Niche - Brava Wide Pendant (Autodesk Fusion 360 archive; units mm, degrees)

design "Brava Wide" references "PCB Single Pendant Canopy"
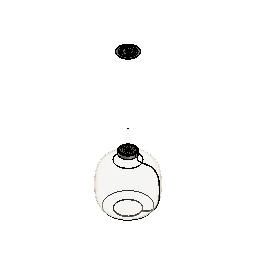
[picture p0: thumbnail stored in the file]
base_feature "Base Feature" bodies "Glass-Brava Wide"
external_derived "ExternalDerived1" bodies "Set Screw", "Strain Relief", "Lead-1", "Lead-2", "Lead-2.1", "Lead-1.1", "Coax", "Stem"
move "Move1"
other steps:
derived_base_feature "Derived Base Feature" bodies "Set Screw", "Strain Relief", "Lead-1", "Lead-2", "Lead-2.1", "Lead-1.1", "Coax", "Stem"
create_component "CreateComponent1"
named bodies: "Glass-Brava Wide", "Set Screw", "Strain Relief", "Lead-1", "Lead-2", "Lead-2.1", "Lead-1.1", "Coax", "Stem", "Strain Relief Cap", "Nylon Gripper (2)", "Cap", "Thumbscrew (1)", "Thumbscrew (2)", "Thumbscrew (3)", "Niche-PCB", "FJ-Plug Cover", "FJ-Plug", "FJ-Plug1.1", "FJ-Plug1.2", "FJ-Plug1.3", "Fj-Plug1.4", "Canopy", "FJ-Port", "FJ-Port1.1", "Spacer", "Universal Mount", "FJ-Port Cover", "Diffuser"

design "FJ Plug - PCB-Hardware"
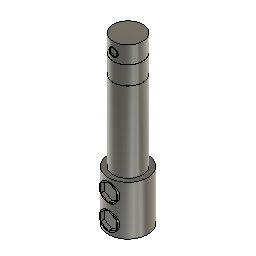
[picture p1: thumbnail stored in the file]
sketch "Sketch1" plane through (0, 0, 0) normal (0, 0, 1) x axis (1, 0, 0)
  circle C1 centre (0, 0) radius 3.048
  point P1 (0, 0)
  point P2 (0, 0)
  coincident P1 P2
  dimension "d1" diameter C1 = 6.096
extrude "Extrude1" new body sketch "Sketch1" along normal blind 34.036
sketch "Sketch2" plane through (0, 0, 0) normal (0, 0, 1) x axis (1, 0, 0)
  circle C1 centre (0, 0) radius 4.064
  point P1 (0, 0)
  point P2 (0, 0)
  coincident P1 P2
  dimension "d4" diameter C1 = 8.128
extrude "Extrude2" add sketch "Sketch2" along normal blind 10.16
sketch "Sketch3" plane through (0, 0, 0) normal (0, 1, 0) x axis (1, 0, 0)
  line L1 (6.35, 0) -> (-6.35, 0)
  line L2 (6.35, -30.48) -> (-6.35, -30.48)
  line L3 (2.54, -30.48) -> (6.35, -30.48)
  line L4 (2.54, -26.67) -> (2.54, -30.48)
  line L5 (6.35, -26.67) -> (2.54, -26.67)
  line L6 (6.35, -30.48) -> (6.35, -26.67)
  horizontal L1
  horizontal L3
  vertical L4
  horizontal L5
  vertical L6
  dimension "d7" = 30.48
revolve "Revolve1" sketch "Sketch3" AlongAngle 360
sketch "Sketch4" plane through (0, 0, 0) normal (0, 1, 0) x axis (1, 0, 0)
  line L1 (2.54, -30.48) -> (3.048, -30.48)
  line L2 (2.54, -26.67) -> (2.54, -30.48)
  line L3 (3.048, -26.67) -> (2.54, -26.67)
  line L4 (3.048, -30.48) -> (3.048, -26.67)
  horizontal L1
  vertical L2
  horizontal L3
  vertical L4
revolve "Revolve2" sketch "Sketch4" AlongAngle 360
chamfer "Chamfer1" distance 0.0254
chamfer "Chamfer2" distance 0.0254
hole "Hole1" HoleDepth 33.401 HoleDiameter 4.826 TipAngle 180
hole "Hole2" HoleDepth 3.81 HoleDiameter 1.778 TipAngle 180
hole "Hole3" HoleDepth 3.81 HoleDiameter 3.81 TipAngle 180
hole "Hole4" HoleDepth 3.81 HoleDiameter 3.81 TipAngle 180
sketch "Sketch5" plane through (0, 0, 0) normal (0, 1, 0) x axis (1, 0, 0)
  circle C1 centre (0, -32.0802) radius 0.889
  dimension "d24" diameter C1 = 1.778
extrude "Extrude3" new body sketch "Sketch5" along normal blind 1.778
move "Move1"
sketch "Sketch6" plane through (0, -3.048, 0) normal (0, -1, 0) x axis (1, 0, 0)
  line L1 (0.7259, 31.6611) -> (0, 31.242)
  line L2 (0.7259, 32.4993) -> (0.7259, 31.6611)
  line L3 (0, 32.9184) -> (0.7259, 32.4993)
  line L4 (-0.7259, 32.4993) -> (0, 32.9184)
  line L5 (-0.7259, 31.6611) -> (-0.7259, 32.4993)
  line L6 (0, 31.242) -> (-0.7259, 31.6611)
  circle C1 centre (0, 32.0802) radius 0.889
  point P2 (0, 32.0802)
  point P9 (0, 32.0802)
  coincident P2 P9
extrude "Extrude4" cut sketch "Sketch6" profile of L1 L2 L3 L4 L5 L6 against normal blind 0.254
sketch "Sketch7" plane through (0, 0, 0) normal (0, 1, 0) x axis (1, 0, 0)
  circle C1 centre (0, -2.4384) radius 1.905
  circle C2 centre (0, -7.5565) radius 1.905
  dimension "d29" diameter C1 = 3.81
  dimension "d30" diameter C2 = 3.81
extrude "Extrude5" new body sketch "Sketch7" profile of C2 along normal blind 3.81
move "Move2"
sketch "Sketch8" plane through (0, -4.064, 0) normal (0, -1, 0) x axis (1, 0, 0)
  line L1 (1.5948, 6.6357) -> (0, 5.715)
  line L2 (1.5948, 8.4772) -> (1.5948, 6.6357)
  line L3 (0, 9.398) -> (1.5948, 8.4772)
  line L4 (-1.5948, 8.4772) -> (0, 9.398)
  line L5 (-1.5948, 6.6357) -> (-1.5948, 8.4772)
  line L6 (0, 5.715) -> (-1.5948, 6.6357)
  circle C1 centre (0, 7.5565) radius 1.905
  point P2 (0, 7.5565)
  point P9 (0, 7.5565)
  coincident P2 P9
extrude "Extrude6" cut sketch "Sketch8" profile of L1 L2 L3 L4 L5 L6 against normal blind 0.762
copy_paste_bodies "CopyPasteBodies2"
move "Move4"
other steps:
base_feature "Base Feature"

design "Flask Petite"
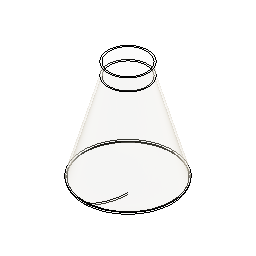
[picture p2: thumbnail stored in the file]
sketch "Sketch1" plane through (0, 0, 0) normal (1, 0, 0) x axis (0, 1, 0)
canvas "Canvas1"
sketch "Sketch2" plane through (0, 0, 0) normal (1, 0, 0) x axis (0, 1, 0)
  line L1 (-5.314, 187.093) -> (-57.384, 187.093)
  line L2 (-57.384, 155.343) -> (-57.384, 187.093)
  line L3 (-121.92, -71.12) -> (-57.384, 155.343)
  line L4 (-5.314, -112.5919) -> (-5.314, 187.093)
  curve K1 (-5.314, -112.5919) -> (-121.92, -74.8854)
  arc A1 centre (-115.3135, -73.0027) radius 6.8695 clockwise from (-121.92, -74.8854) to (-121.92, -71.12)
  point P2 (-57.384, 187.093)
  point P3 (-5.314, 187.093)
  point P4 (-57.384, 155.343)
  horizontal L1
  perpendicular L1 L2
  tangent L3 A1
  perpendicular L1 L4
  dimension "d1" distance P2 P3 = 52.07
  dimension "d2" distance P2 P4 = 31.75
revolve "Revolve1" sketch "Sketch2" AlongAngle 360
fillet "Fillet1" radius 5.08
shell "Shell1" innerThickness 4

design "PCB Single Pendant Canopy" references "Diffuser", "FJ Plug - PCB-Hardware", "FJ Cover - PCB-Hardware", "PCB Cap", "Flask Petite", "PCB Canopy"
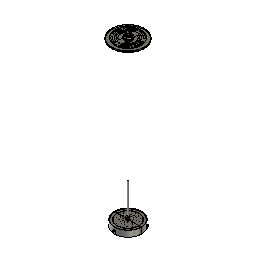
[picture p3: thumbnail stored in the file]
external_derived "ExternalDerived1" bodies "Nylon Gripper", "Set Screw", "Strain Relief", "Lead-1", "Lead-2", "Lead-2.1", "Lead-1.1", "Coax"
external_derived "ExternalDerived2" bodies "FJ-Plug Cover"
move "Move1"
move "Move2" TranslateX 3.175 TranslateY 0.254 TranslateZ 0
move "Move3" TranslateX 0 TranslateY 0 TranslateZ 1092.2
external_derived "ExternalDerived3" bodies "FJ-Plug", "FJ-Plug1.2", "FJ-Plug1.1", "FJ-Plug1.3", "Fj-Plug1.4"
move "Move4" TranslateX 0 TranslateY 0 TranslateZ 1117.6
external_derived "ExternalDerived4" bodies "Nylon Gripper", "Spacer", "Canopy", "FJ-Port", "FJ-Port1.1", "Universal Mount", "FJ-Port Cover", "Lead-1.1"
move "Move5"
move "Move6"
external_derived "ExternalDerived5" bodies "Diffuser"
move "Move7"
external_derived "ExternalDerived6" bodies "Thumbscrew (1)"
align "Align1"
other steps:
derived_base_feature "Derived Base Feature1"
derived_base_feature "Derived Base Feature2" bodies "FJ-Plug Cover"
derived_base_feature "Derived Base Feature3" bodies "FJ-Plug", "FJ-Plug1.1", "FJ-Plug1.2"
derived_base_feature "Derived Base Feature4" bodies "Body1 (1)", "Body1 (1) (1)", "Body2 (1)", "Body1 (2)", "Body1 (3)", "Body1 (4)", "Canopy", "FJ-Port"
derived_base_feature "Derived Base Feature5" bodies "Diffuser"
derived_base_feature "Derived Base Feature6" bodies "Body1", "Thumbscrew (1)"
named bodies: "Nylon Gripper", "Set Screw", "Strain Relief", "Lead-1", "Lead-2", "Lead-2.1", "Lead-1.1", "Coax", "Stem", "stem (2)", "Strain Relief Cap", "Nylon Gripper (2)", "Cap", "Thumbscrew (1)", "Thumbscrew (2)", "Thumbscrew (3)", "Niche-PCB", "FJ-Plug Cover", "FJ-Plug", "FJ-Plug1.1", "FJ-Plug1.2", "FJ-Plug1.3", "Fj-Plug1.4", "Body1 (1)", "Body1 (1) (1)", "Body2 (1)", "Body1 (2)", "Body1 (3)", "Body1 (4)", "Canopy", "FJ-Port", "FJ-Port1.1", "Spacer", "Universal Mount", "FJ-Port Cover", "Diffuser", "Body1"

design "FJ Female"
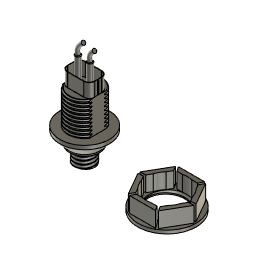
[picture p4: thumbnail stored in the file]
sketch "Sketch1" plane through (0, 0, 0) normal (0, 0, 1) x axis (1, 0, 0)
  circle C1 centre (0, 0) radius 4.445
  point P1 (0, 0)
  point P2 (0, 0)
  coincident P1 P2
  dimension "d1" diameter C1 = 8.89
extrude "Extrude1" new body sketch "Sketch1" along normal blind 6.858
sketch "Sketch2" plane through (0, 0, 6.858) normal (0, 0, 1) x axis (-1, 0, 0)
  circle C1 centre (0, 0) radius 4.445
  circle C2 centre (0, 0) radius 6.985
  point P1 (0, 0)
  point P3 (0, 0)
  coincident P1 P3
  dimension "d4" diameter C2 = 13.97
extrude "Extrude2" add sketch "Sketch2" along normal blind 1.27
work_plane "WorkPlane1" AlongDistance 5.08
sketch "Sketch3" plane through (0, 0, 13.208) normal (0, 0, 1) x axis (1, 0, 0)
  circle C1 centre (0, 0) radius 11.43
  point P1 (0, 0)
  point P2 (0, 0)
  coincident P1 P2
  dimension "d8" diameter C1 = 22.86
loft "Loft1" sketch "Sketch3"
extrude "Extrude3" add of existing geometry blind 1.778
sketch "Sketch4" plane through (0, 0, 14.986) normal (0, 0, 1) x axis (-1, 0, 0)
  circle C1 centre (0, 0) radius 11.43
  circle C2 centre (0, 0) radius 7.62
  point P1 (0, 0)
  point P3 (0, 0)
  coincident P1 P3
  dimension "d11" diameter C2 = 15.24
extrude "Extrude4" add sketch "Sketch4" profile of C2 along normal blind 15.24
sketch "Sketch5" plane through (0, 0, 30.226) normal (0, 0, 1) x axis (-1, 0, 0)
  line L1 (6.35, 0) -> (0, 0)
  line L2 (-6.35, 0) -> (0, 0)
  line L3 (6.35, -4.2121) -> (6.35, 0)
  line L4 (6.35, 4.2121) -> (6.35, 0)
  line L5 (-6.35, -4.2121) -> (-6.35, 0)
  line L6 (-6.35, 4.2121) -> (-6.35, 0)
  circle C1 centre (0, 0) radius 7.62
  point P2 (0, 0)
  point P3 (0, 0)
  point P5 (0, 0)
  point P7 (6.35, -4.2121)
  point P8 (6.35, 4.2121)
  point P9 (-6.35, -4.2121)
  point P10 (-6.35, 0)
  point P11 (-6.35, 4.2121)
  point P4 (6.35, 0)
  point P6 (-6.35, 0)
  coincident P2 P3
  horizontal L1
  coincident P2 P5
  parallel L1 L2
  coincident C1 P7
  perpendicular L1 L3
  coincident C1 P8
  perpendicular L1 L4
  coincident C1 P9
  perpendicular L2 L5
  coincident L2 P10
  perpendicular L2 L6
  coincident C1 P11
  dimension "d14" distance P3 P4 = 6.35
  dimension "d15" distance P5 P6 = 6.35
extrude "Extrude5" cut sketch "Sketch5" profile of C1 L3 L4 L5 L6 against normal blind 15.24
sketch "Sketch6" plane through (0, 0, 30.226) normal (0, 0, 1) x axis (-1, 0, 0)
  line L1 (-6.35, -4.2121) -> (-6.35, 4.2121)
  line L2 (6.35, 4.2121) -> (6.35, -4.2121)
  line L3 (-6.35, -4.2121) -> (6.35, -4.2121)
  line L4 (6.35, 4.2121) -> (-6.35, 4.2121)
  line L5 (6.35, -4.2121) -> (6.35, 4.2121)
  line L6 (-6.35, 4.2121) -> (-6.35, -4.2121)
  line L7 (-6.223, 4.064) -> (6.223, 4.064)
  line L8 (-6.223, -4.064) -> (-6.223, 4.064)
  line L9 (6.223, -4.064) -> (-6.223, -4.064)
  line L10 (6.223, 4.064) -> (6.223, -4.064)
  line L11 (-6.223, -4.064) -> (6.223, 4.064)
  line L12 (6.223, -4.064) -> (-6.223, 4.064)
  arc A1 centre (0, 0) radius 7.62 clockwise from (6.35, -4.2121) to (-6.35, -4.2121)
  arc A2 centre (0, 0) radius 7.62 clockwise from (-6.35, 4.2121) to (6.35, 4.2121)
  point P4 (6.35, -4.2121)
  point P7 (6.35, -4.2121)
  point P3 (-6.35, -4.2121)
  point P8 (-6.35, -4.2121)
  point P2 (-6.35, 4.2121)
  point P9 (-6.35, 4.2121)
  point P6 (6.35, 4.2121)
  point P10 (6.35, 4.2121)
  point P15 (0, 0)
  point P5 (0, 0)
  point P13 (-6.223, -4.064)
  point P14 (6.223, -4.064)
  point P12 (-6.223, 4.064)
  coincident P4 P7
  coincident P3 P8
  coincident P2 P9
  coincident P6 P10
  perpendicular L7 L8
  parallel L7 L9
  parallel L8 L10
  horizontal L7
  coincident L11 P15
  coincident L12 P15
  coincident P5 P15
  dimension "d18" distance P13 P14 = 12.446
  dimension "d19" distance P12 P13 = 8.128
extrude "Extrude6" add sketch "Sketch6" profile of L1 L2 L3 L4 L5 L6 L7 L8 L9 L10 along normal blind 6.35
fillet "Fillet1" radius 2.54
sketch "Sketch7" plane through (6.35, 0, 0) normal (1, 0, 0) x axis (0, 1, 0)
  line L1 (1.6721, 36.576) -> (1.6721, 30.226)
  line L2 (-1.6721, 36.576) -> (1.6721, 36.576)
  line L3 (-1.6721, 30.226) -> (-1.6721, 36.576)
  line L4 (-4.2121, 30.226) -> (-1.6721, 30.226)
  line L5 (-4.2121, 14.986) -> (-4.2121, 30.226)
  line L6 (4.2121, 14.986) -> (-4.2121, 14.986)
  line L7 (4.2121, 30.226) -> (4.2121, 14.986)
  line L8 (1.6721, 30.226) -> (4.2121, 30.226)
  line L9 (0.254, 36.576) -> (-0.2492, 36.576)
  line L10 (0.254, 30.226) -> (0.254, 36.576)
  line L11 (-0.2492, 30.226) -> (0.254, 30.226)
  line L12 (-0.2492, 36.576) -> (-0.2492, 30.226)
  point P10 (-0.2492, 36.576)
  horizontal L9
  vertical L10
  horizontal L11
  vertical L12
  coincident L2 P10
extrude "Extrude7" cut sketch "Sketch7" profile of L2 L9 L10 L11 L12 against normal blind 0.508
thread "Thread1"
fillet "Fillet2" radius 0.635
thread "Thread2"
sketch "Sketch8" plane through (0, 0, 30.226) normal (0, 0, 1) x axis (-1, 0, 0)
  line L1 (-6.223, -1.524) -> (-6.223, -0.254)
  line L2 (3.683, -4.064) -> (-3.683, -4.064)
  line L3 (6.223, 1.524) -> (6.223, -1.524)
  line L4 (-3.683, 4.064) -> (3.683, 4.064)
  line L5 (-6.223, 0.2492) -> (-6.223, 1.524)
  line L6 (-6.35, 0.2492) -> (-6.223, 0.2492)
  line L7 (-6.35, -0.254) -> (-6.35, 0.2492)
  line L8 (-6.223, -0.254) -> (-6.35, -0.254)
  arc A1 centre (-3.683, -1.524) radius 2.54 clockwise from (-3.683, -4.064) to (-6.223, -1.524)
  arc A2 centre (3.683, -1.524) radius 2.54 clockwise from (6.223, -1.524) to (3.683, -4.064)
  arc A3 centre (3.683, 1.524) radius 2.54 clockwise from (3.683, 4.064) to (6.223, 1.524)
  arc A4 centre (-3.683, 1.524) radius 2.54 clockwise from (-6.223, 1.524) to (-3.683, 4.064)
  circle C1 centre (3.048, 0) radius 1.27
  circle C2 centre (-2.54, 0) radius 1.27
  dimension "d26" diameter C1 = 2.54
  dimension "d27" diameter C2 = 2.54
extrude "Extrude8" add sketch "Sketch8" profile of C1 C2 along normal blind 11.43
sketch "Sketch9" plane through (0, 0, 0) normal (0, 1, 0) x axis (1, 0, 0)
  curve K1 (4.572, -46.99) -> (2.54, -41.656)
  curve K2 (-0.508, -47.752) -> (-3.048, -41.656)
pipe "Pipe1" SectionSize 1.778 SectionThickness 0.0762
pipe "Pipe2" SectionSize 1.778 SectionThickness 0.0762
sketch "Sketch10" plane through (0, 0, 0) normal (0, 0, 1) x axis (1, 0, 0)
  circle C1 centre (38.1, 0) radius 13.462
  dimension "d38" diameter C1 = 26.924
extrude "Extrude9" new body sketch "Sketch10" along normal blind 1.524
sketch "Sketch11" plane through (0, 0, 1.524) normal (0, 0, 1) x axis (-1, 0, 0)
  circle C1 centre (-38.1, 0) radius 13.462
  circle C2 centre (-38.1, 0) radius 9.271
  concentric C1 C2
  dimension "d41" diameter C2 = 18.542
extrude "Extrude10" cut sketch "Sketch11" profile of C2 against normal blind 7.62
sketch "Sketch12" plane through (0, 0, 1.524) normal (0, 0, 1) x axis (-1, 0, 0)
  line L1 (-24.9018, 0) -> (-31.5009, -11.43)
  line L2 (-31.5009, 11.43) -> (-24.9018, 0)
  line L3 (-44.6991, 11.43) -> (-31.5009, 11.43)
  line L4 (-51.2982, 0) -> (-44.6991, 11.43)
  line L5 (-44.6991, -11.43) -> (-51.2982, 0)
  line L6 (-31.5009, -11.43) -> (-44.6991, -11.43)
  line L7 (-27.3948, 0) -> (-32.7474, -9.271)
  line L8 (-32.7474, 9.271) -> (-27.3948, 0)
  line L9 (-43.4526, 9.271) -> (-32.7474, 9.271)
  line L10 (-48.8052, 0) -> (-43.4526, 9.271)
  line L11 (-43.4526, -9.271) -> (-48.8052, 0)
  line L12 (-32.7474, -9.271) -> (-43.4526, -9.271)
  circle C1 centre (-38.1, 0) radius 9.271
  circle C2 centre (-38.1, 0) radius 13.462
  point P2 (-38.1, 0)
  point P9 (-38.1, 0)
  point P16 (-38.1, 0)
  coincident P2 P9
  coincident P9 P16
extrude "Extrude11" add sketch "Sketch12" profile of L1 L2 L3 L4 L5 L6 L7 L8 L9 L10 L11 L12 along normal blind 7.112
thread "Thread3"
sketch "Sketch13" plane through (0, 0, 8.636) normal (0, 0, 1) x axis (-1, 0, 0)
  line L1 (-43.4526, -9.271) -> (-32.7474, -9.271)
  line L2 (-48.8052, 0) -> (-43.4526, -9.271)
  line L3 (-43.4526, 9.271) -> (-48.8052, 0)
  line L4 (-32.7474, 9.271) -> (-43.4526, 9.271)
  line L5 (-27.3948, 0) -> (-32.7474, 9.271)
  line L6 (-32.7474, -9.271) -> (-27.3948, 0)
  line L7 (-31.5009, -11.43) -> (-44.6991, -11.43)
  line L8 (-24.9018, 0) -> (-31.5009, -11.43)
  line L9 (-31.5009, 11.43) -> (-24.9018, 0)
  line L10 (-44.6991, 11.43) -> (-31.5009, 11.43)
  line L11 (-51.2982, 0) -> (-44.6991, 11.43)
  line L12 (-44.6991, -11.43) -> (-51.2982, 0)
sketch "Sketch14" plane through (0, 0, 8.636) normal (0, 0, 1) x axis (-1, 0, 0)
  circle C1 centre (-38.1, 0) radius 9.525
  dimension "d46" diameter C1 = 19.05
extrude "Extrude12" cut sketch "Sketch14" against normal blind 7.112
sketch "Sketch15" plane through (0, 0, 8.636) normal (0, 0, 1) x axis (-1, 0, 0)
  line L1 (-51.2982, 0) -> (-44.6991, 11.43)
  line L2 (-43.4526, 9.271) -> (-48.8052, 0)
  line L3 (-32.7474, 9.271) -> (-43.4526, 9.271)
  line L4 (-44.6991, 11.43) -> (-31.5009, 11.43)
  line L5 (-44.1911, 11.43) -> (-42.7995, 9.271)
  line L6 (-40.2139, 9.271) -> (-42.7995, 9.271)
  line L7 (-43.7181, 8.8112) -> (-45.0232, 10.8687)
  line L8 (-43.4526, 9.271) -> (-42.7995, 9.271)
  line L9 (-43.7181, 8.8112) -> (-43.4526, 9.271)
  line L10 (-45.0232, 10.8687) -> (-44.6991, 11.43)
  line L11 (-44.1911, 11.43) -> (-44.6991, 11.43)
  line L12 (-48.5398, -0.4598) -> (-50.9742, -0.5613)
  line L13 (-48.5398, -0.4598) -> (-48.8052, 0)
  line L14 (-48.8052, 0) -> (-48.4787, 0.5657)
  line L15 (-51.0442, 0.4399) -> (-48.4787, 0.5657)
  line L16 (-51.0442, 0.4399) -> (-51.2982, 0)
  line L17 (-50.9742, -0.5613) -> (-51.2982, 0)
  line L18 (-42.9217, -9.271) -> (-44.051, -11.43)
  line L19 (-42.9217, -9.271) -> (-43.4526, -9.271)
  line L20 (-43.4526, -9.271) -> (-43.7792, -8.7053)
  line L21 (-44.9531, -10.9901) -> (-43.7792, -8.7053)
  line L22 (-44.9531, -10.9901) -> (-44.6991, -11.43)
  line L23 (-44.051, -11.43) -> (-44.6991, -11.43)
  line L24 (-32.4819, -8.8112) -> (-31.1768, -10.8687)
  line L25 (-32.4819, -8.8112) -> (-32.7474, -9.271)
  line L26 (-32.7474, -9.271) -> (-33.4005, -9.271)
  line L27 (-32.0089, -11.43) -> (-33.4005, -9.271)
  line L28 (-32.0089, -11.43) -> (-31.5009, -11.43)
  line L29 (-31.1768, -10.8687) -> (-31.5009, -11.43)
  line L30 (-27.6603, 0.4598) -> (-25.2258, 0.5613)
  line L31 (-27.6603, 0.4598) -> (-27.3948, 0)
  line L32 (-27.3948, 0) -> (-27.7214, -0.5657)
  line L33 (-25.1558, -0.4399) -> (-27.7214, -0.5657)
  line L34 (-25.1558, -0.4399) -> (-24.9018, 0)
  line L35 (-25.2258, 0.5613) -> (-24.9018, 0)
  line L36 (-33.2783, 9.271) -> (-32.149, 11.43)
  line L37 (-33.2783, 9.271) -> (-32.7474, 9.271)
  line L38 (-32.7474, 9.271) -> (-32.4208, 8.7053)
  line L39 (-31.2469, 10.9901) -> (-32.4208, 8.7053)
  line L40 (-31.2469, 10.9901) -> (-31.5009, 11.43)
  line L41 (-32.149, 11.43) -> (-31.5009, 11.43)
  point P10 (-42.7995, 9.271)
  point P12 (-45.0232, 10.8687)
  point P13 (-43.7181, 8.8112)
  point P5 (-43.4526, 9.271)
  point P14 (-43.4526, 9.271)
  point P16 (-44.1911, 11.43)
  point P9 (-44.6991, 11.43)
  point P15 (-44.6991, 11.43)
  horizontal L6
  coincident L3 P10
  coincident L1 P12
  coincident L2 P13
  coincident P5 P14
  coincident L4 P16
  coincident P9 P15
  coincident L4 P16
  dimension "d50" distance P15 P16 = 0.508
  dimension "d54" C-Pattern1-Angle = 360
extrude "Extrude13" cut sketch "Sketch15" profile of L1 L2 L3 L4 L5 L7 L8 L9 L10 L11 L12 L13 L14 L15 L16 L17 L18 L19 L20 L21 L22 L23 L24 L25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 against normal blind 7.112

design "FJ Cover - PCB-Hardware"
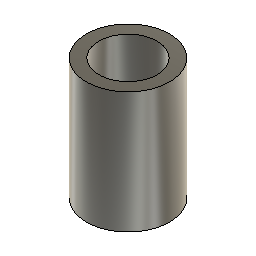
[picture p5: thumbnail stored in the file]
sketch "Sketch1" plane through (0, 0, 0) normal (0, 0, 1) x axis (1, 0, 0)
  circle C1 centre (0, 0) radius 6.35
  point P1 (0, 0)
  point P2 (0, 0)
  coincident P1 P2
  dimension "d1" diameter C1 = 12.7
extrude "Extrude1" new body sketch "Sketch1" along normal blind 18.542
hole "Hole1" HoleDepth 13.97 HoleDiameter 8.89 TipAngle 180
hole "Hole2" HoleDepth 13.97 HoleDiameter 3.556 TipAngle 180

design "PCB Canopy" references "FJ Cover - PCB-Hardware", "Spacer - PCB-Hardware", "Universal Mounting Bracket - PCB-Hardware", "FJ Female", "Canopy - PCB-Hardware", "Port Cover - PCB-Hardware"
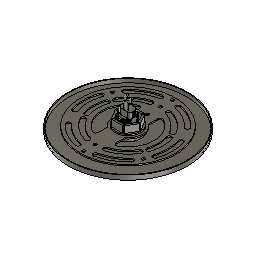
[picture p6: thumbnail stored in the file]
external_derived "ExternalDerived"
external_derived "ExternalDerived"
external_derived "ExternalDerived3" bodies "Body1 (1)"
external_derived "ExternalDerived4"
external_derived "ExternalDerived5"
move "Move1"
move "Move2"
move "Move3"
move "Move4"
move "Move5"
move "Move6"
move "Move7"
move "Move8"
external_derived "ExternalDerived6"
align "Align1"
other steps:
derived_base_feature "Derived Base Feature" bodies "Body1"
derived_base_feature "Derived Base Feature" bodies "Body1 (1)", "Body2"
derived_base_feature "Derived Base Feature3" bodies "Body1 (2)", "Body1 (1)"
derived_base_feature "Derived Base Feature4" bodies "Body1 (3)"
derived_base_feature "Derived Base Feature5" bodies "Body1 (4)"
derived_base_feature "Derived Base Feature6" bodies "Body1 (5)"
named bodies: "Body1", "Body1 (1)", "Body2", "Body1 (2)", "Body1 (3)", "Body1 (4)", "Body1 (5)"

design "Spacer - PCB-Hardware"
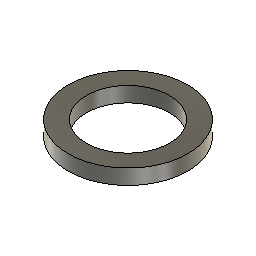
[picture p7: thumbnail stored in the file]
sketch "Sketch1" plane through (0, 0, 0) normal (0, 0, 1) x axis (1, 0, 0)
  circle C1 centre (0, 0) radius 14.097
  circle C2 centre (0, 0) radius 9.779
  point P1 (0, 0)
  point P2 (0, 0)
  point P3 (0, 0)
  coincident P1 P2
  coincident P1 P3
  dimension "d1" diameter C1 = 28.194
  dimension "d2" diameter C2 = 19.558
extrude "Extrude1" new body sketch "Sketch1" along normal blind 3.556

design "Universal Mounting Bracket - PCB-Hardware"
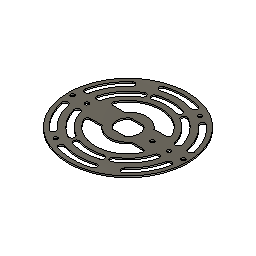
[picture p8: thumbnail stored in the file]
sketch "Sketch1" plane through (0, 0, 0) normal (0, 0, 1) x axis (1, 0, 0)
  circle C1 centre (0, 0) radius 50.8
  arc A1 centre (0, 0) radius 42.545 clockwise from (-13.1471, 40.4627) to (13.1471, 40.4627)
  arc A2 centre (0, 0) radius 47.371 clockwise from (-14.6384, 45.0525) to (14.6384, 45.0525)
  arc A3 centre (-13.8928, 42.7576) radius 2.413 clockwise from (-13.1471, 40.4627) to (-14.6384, 45.0525)
  arc A4 centre (13.8928, 42.7576) radius 2.413 clockwise from (14.6384, 45.0525) to (13.1471, 40.4627)
  arc A5 centre (0, 0) radius 47.371 clockwise from (-46.3358, 9.849) to (-31.6974, 35.2035)
  arc A6 centre (0, 0) radius 42.545 clockwise from (-41.6153, 8.8456) to (-28.4682, 31.6171)
  arc A7 centre (-43.9756, 9.3473) radius 2.413 clockwise from (-41.6153, 8.8456) to (-46.3358, 9.849)
  arc A8 centre (-30.0828, 33.4103) radius 2.413 clockwise from (-31.6974, 35.2035) to (-28.4682, 31.6171)
  arc A9 centre (0, 0) radius 47.371 clockwise from (-31.6974, -35.2035) to (-46.3358, -9.849)
  arc A10 centre (0, 0) radius 42.545 clockwise from (-28.4682, -31.6171) to (-41.6153, -8.8456)
  arc A11 centre (-30.0828, -33.4103) radius 2.413 clockwise from (-28.4682, -31.6171) to (-31.6974, -35.2035)
  arc A12 centre (-43.9756, -9.3473) radius 2.413 clockwise from (-46.3358, -9.849) to (-41.6153, -8.8456)
  arc A13 centre (0, 0) radius 47.371 clockwise from (14.6384, -45.0525) to (-14.6384, -45.0525)
  arc A14 centre (0, 0) radius 42.545 clockwise from (13.1471, -40.4627) to (-13.1471, -40.4627)
  arc A15 centre (13.8928, -42.7576) radius 2.413 clockwise from (13.1471, -40.4627) to (14.6384, -45.0525)
  arc A16 centre (-13.8928, -42.7576) radius 2.413 clockwise from (-14.6384, -45.0525) to (-13.1471, -40.4627)
  arc A17 centre (0, 0) radius 47.371 clockwise from (46.3358, -9.849) to (31.6974, -35.2035)
  arc A18 centre (0, 0) radius 42.545 clockwise from (41.6153, -8.8456) to (28.4682, -31.6171)
  arc A19 centre (43.9756, -9.3473) radius 2.413 clockwise from (41.6153, -8.8456) to (46.3358, -9.849)
  arc A20 centre (30.0828, -33.4103) radius 2.413 clockwise from (31.6974, -35.2035) to (28.4682, -31.6171)
  arc A21 centre (0, 0) radius 47.371 clockwise from (31.6974, 35.2035) to (46.3358, 9.849)
  arc A22 centre (0, 0) radius 42.545 clockwise from (28.4682, 31.6171) to (41.6153, 8.8456)
  arc A23 centre (30.0828, 33.4103) radius 2.413 clockwise from (28.4682, 31.6171) to (31.6974, 35.2035)
  arc A24 centre (43.9756, 9.3473) radius 2.413 clockwise from (46.3358, 9.849) to (41.6153, 8.8456)
  arc A25 centre (0, 0) radius 32.385 clockwise from (-31.2224, 8.5995) to (-16.1925, 28.0462)
  arc A26 centre (0, 0) radius 37.338 clockwise from (-35.9514, 10.0809) to (-18.669, 32.3357)
  arc A27 centre (0, 0) radius 32.385 clockwise from (16.1925, 28.0462) to (31.2224, 8.5995)
  arc A28 centre (0, 0) radius 32.385 clockwise from (-10.0075, 30.8) to (10.0075, 30.8)
  arc A29 centre (0, 0) radius 37.338 clockwise from (18.669, 32.3357) to (35.9514, 10.0809)
  arc A30 centre (0, 0) radius 37.338 clockwise from (-11.5381, 35.5105) to (11.5381, 35.5105)
  arc A31 centre (-33.5467, 9.4685) radius 2.4814 clockwise from (-31.1111, 8.9939) to (-35.9167, 10.2037)
  arc A32 centre (-17.4307, 30.1909) radius 2.4765 clockwise from (-18.669, 32.3357) to (-16.1925, 28.0462)
  arc A33 centre (-10.7728, 33.1553) radius 2.4765 clockwise from (-10.0075, 30.8) to (-11.5381, 35.5105)
  arc A34 centre (10.7728, 33.1553) radius 2.4765 clockwise from (11.5381, 35.5105) to (10.0075, 30.8)
  arc A35 centre (17.4307, 30.1909) radius 2.4765 clockwise from (16.1925, 28.0462) to (18.669, 32.3357)
  arc A36 centre (33.5467, 9.4685) radius 2.4814 clockwise from (35.9167, 10.2037) to (31.1111, 8.9939)
  arc A37 centre (-33.5467, -9.4685) radius 2.4814 clockwise from (-35.9167, -10.2037) to (-31.1111, -8.9939)
  arc A38 centre (0, 0) radius 37.338 clockwise from (-18.669, -32.3357) to (-35.9514, -10.0809)
  arc A39 centre (0, 0) radius 32.385 clockwise from (-16.1925, -28.0462) to (-31.2224, -8.5995)
  arc A40 centre (-17.4307, -30.1909) radius 2.4765 clockwise from (-16.1925, -28.0462) to (-18.669, -32.3357)
  arc A41 centre (-10.7728, -33.1553) radius 2.4765 clockwise from (-11.5381, -35.5105) to (-10.0075, -30.8)
  arc A42 centre (0, 0) radius 37.338 clockwise from (11.5381, -35.5105) to (-11.5381, -35.5105)
  arc A43 centre (0, 0) radius 32.385 clockwise from (10.0075, -30.8) to (-10.0075, -30.8)
  arc A44 centre (10.7728, -33.1553) radius 2.4765 clockwise from (10.0075, -30.8) to (11.5381, -35.5105)
  arc A45 centre (17.4307, -30.1909) radius 2.4765 clockwise from (18.669, -32.3357) to (16.1925, -28.0462)
  arc A46 centre (0, 0) radius 37.338 clockwise from (35.9514, -10.0809) to (18.669, -32.3357)
  arc A47 centre (0, 0) radius 32.385 clockwise from (31.2224, -8.5995) to (16.1925, -28.0462)
  arc A48 centre (33.5467, -9.4685) radius 2.4814 clockwise from (31.1111, -8.9939) to (35.9167, -10.2037)
  point P1 (0, 0)
  point P2 (0, 0)
  point P71 (-35.9514, 10.0809)
  point P72 (-31.2224, 8.5995)
  point P73 (35.9514, 10.0809)
  point P74 (31.2224, 8.5995)
  point P75 (-31.1111, 8.9939)
  point P76 (-35.9167, 10.2037)
  point P77 (35.9167, 10.2037)
  point P78 (31.1111, 8.9939)
  coincident P1 P2
  concentric C1 A2
  concentric A1 A2
  concentric A17 A26
  concentric A25 A26
  concentric A25 A27
  concentric A26 A29
  concentric A27 A28
  concentric A29 A30
  coincident P71 A31
  coincident P72 A31
  coincident P73 A36
  coincident P74 A36
  coincident A25 P75
  coincident A26 P76
  coincident A29 P77
  coincident A27 P78
  dimension "d1" diameter C1 = 101.6
  dimension "d2" diameter A2 = 94.742
  dimension "d11" diameter A26 = 74.676
  dimension "d12" diameter A25 = 64.77
  dimension "d10" C-Pattern1-Angle = 360
sketch "Sketch2" plane through (0, 0, 0) normal (0, 0, 1) x axis (1, 0, 0)
  line L1 (5.3986, -8.001) -> (-5.3986, -8.001)
  line L2 (5.3986, 8.001) -> (-5.3986, 8.001)
  arc A1 centre (0, 0) radius 9.652 clockwise from (-5.3986, -8.001) to (-5.3986, 8.001)
  arc A2 centre (0, 0) radius 9.652 clockwise from (5.3986, 8.001) to (5.3986, -8.001)
  point P1 (0, 0)
  point P2 (0, 0)
  coincident P1 P2
  concentric A1 A2
  dimension "d6" diameter A1 = 19.304
sketch "Sketch3" plane through (0, 0, 0) normal (0, 0, 1) x axis (1, 0, 0)
  line L1 (-12.5409, 9.525) -> (-22.2072, 9.525)
  line L2 (22.2072, 9.525) -> (12.5409, 9.525)
  line L3 (-12.5409, -9.525) -> (-22.2072, -9.525)
  line L4 (22.2072, -9.525) -> (12.5409, -9.525)
  arc A1 centre (0, 0) radius 15.748 clockwise from (12.5409, -9.525) to (-12.5409, -9.525)
  arc A2 centre (0, 0) radius 15.748 clockwise from (-12.5409, 9.525) to (12.5409, 9.525)
  arc A3 centre (0, 0) radius 27.813 clockwise from (24.4391, -13.2776) to (-24.4391, -13.2776)
  arc A4 centre (0, 0) radius 27.813 clockwise from (-24.4391, 13.2776) to (24.4391, 13.2776)
  arc A5 centre (-22.2072, 12.065) radius 2.54 clockwise from (-22.2072, 9.525) to (-24.4391, 13.2776)
  arc A6 centre (22.2072, 12.065) radius 2.54 clockwise from (24.4391, 13.2776) to (22.2072, 9.525)
  arc A7 centre (-22.2072, -12.065) radius 2.54 clockwise from (-24.4391, -13.2776) to (-22.2072, -9.525)
  arc A8 centre (22.2072, -12.065) radius 2.54 clockwise from (22.2072, -9.525) to (24.4391, -13.2776)
  point P1 (0, 0)
  point P2 (0, 0)
  point P5 (12.5409, 9.525)
  coincident P1 P2
  concentric A1 A3
  coincident P5 A1
  collinear L1 L2
  collinear L3 L4
  concentric A1 A2
  concentric A3 A4
  tangent L1 A5
  tangent A4 A5
  tangent L2 A6
  tangent A4 A6
  equal A5 A6
  tangent L3 A7
  tangent A3 A7
  equal A5 A7
  tangent L4 A8
  tangent A3 A8
  equal A5 A8
  dimension "d17" diameter A3 = 55.626
  dimension "d18" diameter A1 = 31.496
  dimension "d37" radius A5 = 2.54
sketch "Sketch4" plane through (0, 0, 0) normal (0, 0, 1) x axis (1, 0, 0)
  circle C1 centre (22.479, 38.9348) radius 1.651
  circle C2 centre (-22.479, -38.9348) radius 1.651
  circle C3 centre (-34.8615, 0) radius 1.651
  circle C4 centre (-47.117, 0) radius 1.651
  circle C5 centre (34.8615, 0) radius 1.651
  circle C6 centre (47.117, 0) radius 1.651
  circle C7 centre (20.701, 0) radius 1.651
  dimension "d36" diameter C7 = 3.302
  dimension "d25" C-Pattern2-Angle = 180
extrude "Extrude1" new body sketch "Sketch1" profile of C1 A2 A1 A3 A4 A5 A6 A7 A8 A9 A10 A11 A12 A13 A14 A15 A16 A17 A18 A19 A20 A21 A22 A23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 along normal blind 1.27
extrude "Extrude2" cut sketch "Sketch3" + "Sketch2" profile of S2:A2 S2:L1 S2:L2 S1:A4 S1:A2 S1:L4 S1:L2 S1:A5 S1:A6 S1:A7 S1:A8 blind 1.27
extrude "Extrude3" cut sketch "Sketch4" along normal blind 1.27

design "Port Cover - PCB-Hardware"
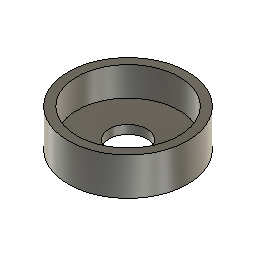
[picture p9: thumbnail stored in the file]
sketch "Sketch1" plane through (0, 0, 0) normal (0, 0, 1) x axis (1, 0, 0)
  circle C1 centre (0, 0) radius 14.097
  point P1 (0, 0)
  point P2 (0, 0)
  coincident P1 P2
  dimension "d1" diameter C1 = 28.194
extrude "Extrude1" new body sketch "Sketch1" along normal blind 8.89
shell "Shell1" innerThickness 2.032
hole "Hole1" HoleDepth 22.86 HoleDiameter 8.89 TipAngle 118

design "PCB Cap"
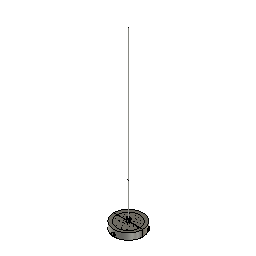
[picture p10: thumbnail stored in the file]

design "Canopy - PCB-Hardware"
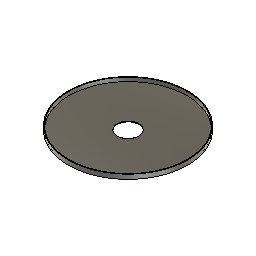
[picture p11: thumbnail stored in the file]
sketch "Sketch1" plane through (0, 0, 0) normal (0, 0, 1) x axis (1, 0, 0)
  circle C1 centre (0, 0) radius 63.5
  point P1 (0, 0)
  point P2 (0, 0)
  coincident P1 P2
extrude "Extrude1" new body sketch "Sketch1" along normal blind 4.826
shell "Shell1" innerThickness 0.762
hole "Hole1" HoleDepth 22.86 HoleDiameter 22.86 TipAngle 118

design "Diffuser"
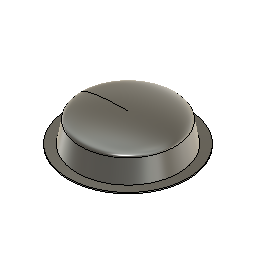
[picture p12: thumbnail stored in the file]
sketch "Sketch1" plane through (0, 0, 0) normal (0, 1, 0) x axis (1, 0, 0)
sketch "Sketch2" plane through (0, 0, 0) normal (0, 0, 1) x axis (1, 0, 0)
  circle C1 centre (0, 0) radius 43.18
  point P1 (0, 0)
  point P2 (0, 0)
  coincident P1 P2
  dimension "d1" diameter C1 = 86.36
sketch "Sketch4" plane through (0, 0, 0) normal (0, 0, 1) x axis (1, 0, 0)
  circle C1 centre (0, 0) radius 50.8
  point P1 (0, 0)
  point P2 (0, 0)
  coincident P1 P2
  dimension "d2" diameter C1 = 101.6
extrude "Extrude1" new body sketch "Sketch4" along normal blind 1.016
sketch "Sketch5" plane through (0, 0, 1.016) normal (0, 0, 1) x axis (-1, 0, 0)
  circle C1 centre (0, 0) radius 50.8
  circle C2 centre (0, 0) radius 42.545
  concentric C1 C2
  dimension "d5" diameter C2 = 85.09
sketch "Sketch8" plane through (0, 0, 1.016) normal (0, 0, 1) x axis (-1, 0, 0)
  circle C1 centre (0, 0) radius 42.545
sketch "Sketch11" plane through (0, 0, 0) normal (0, 1, 0) x axis (1, 0, 0)
sketch "Sketch14" plane through (0, 0, 0) normal (0, 1, 0) x axis (1, 0, 0)
sketch "Sketch15" plane through (0, 0, 1.016) normal (0, 0, 1) x axis (-1, 0, 0)
  line L1 (-42.545, 0) -> (0, 0)
  circle C1 centre (0, 0) radius 42.545
  point P1 (0, 0)
  point P3 (0, 0)
  point P4 (-42.545, 0)
  coincident P1 P3
  coincident C1 P4
  horizontal L1
sketch "Sketch16" plane through (0, 0, 0) normal (0, 0, -1) x axis (1, 0, 0)
  circle C1 centre (0, 0) radius 50.8
sketch "Sketch17" plane through (0, 0, 0) normal (0, 1, 0) x axis (1, 0, 0)
  line L1 (0, -18.8361) -> (40.0012, -18.8361)
  line L2 (0, -1.016) -> (43.18, -1.016)
  line L3 (40.0012, -18.8361) -> (43.18, -1.016)
  line L4 (0, -1.016) -> (0, -25.146)
  line L5 (0, -1.016) -> (43.18, -1.016)
  line L6 (0, -25.1861) -> (0, -1.016)
  curve K1 (0, -25.1861) -> (0, -12.4861)
  curve K2 (40.0012, -18.8361) -> (-40.0012, -18.8361)
  line L7 (0, -12.4861) -> (0, -25.146)
  closed curve K3 centre (0, -18.8361)
  point P3 (0, -1.016)
  point P6 (0, -1.016)
  point P9 (0, -1.016)
  point P10 (0, -1.016)
  point P8 (0, -12.4861)
  point P7 (0, -25.1861)
  point P14 (-40.0012, -18.8361)
  point P11 (40.0012, -18.8361)
  point P4 (43.18, -1.016)
  coincident P3 P6
  coincident P3 P9
  perpendicular L2 L4
  coincident P3 P10
  perpendicular L5 L6
  horizontal L1
  perpendicular L1 K1
  coincident P8 K3
  coincident P7 K3
  coincident K3 P14
  coincident P11 K3
  parallel K1 L7
  dimension "d17" distance P3 P4 = 43.18
revolve "Revolve4" sketch "Sketch17" AlongAngle 360
shell "Shell5" innerThickness 1.016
